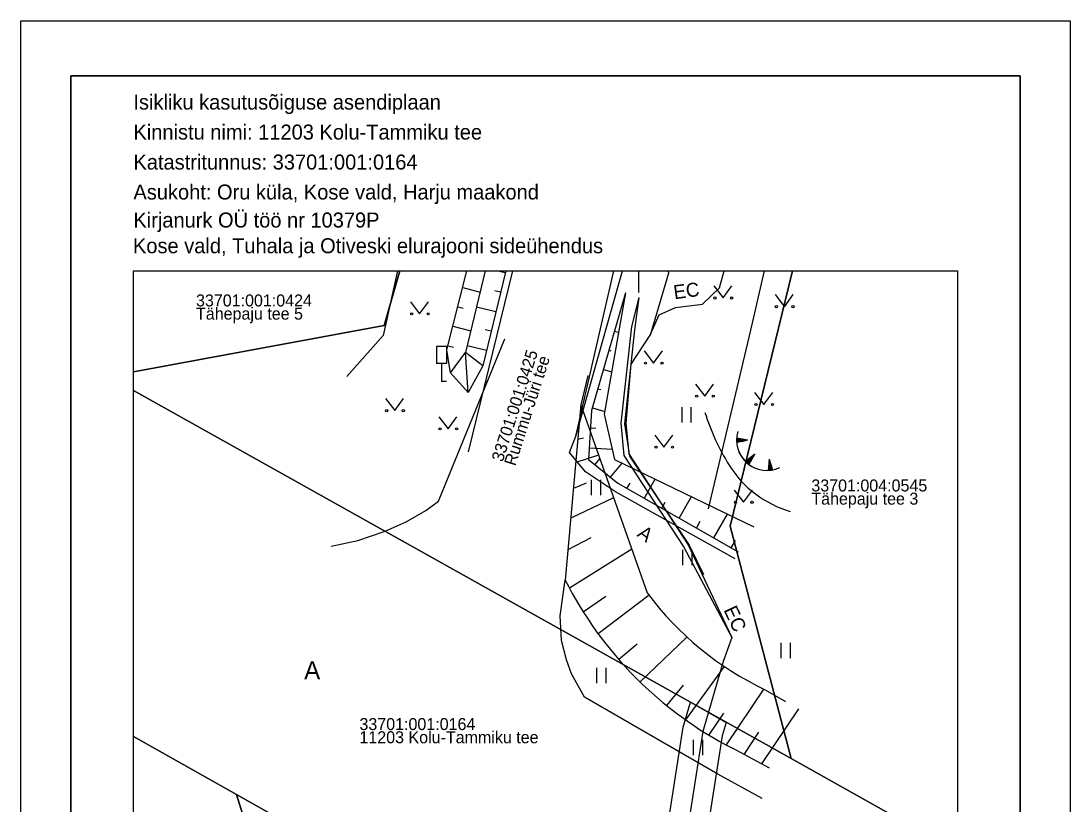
# Model space of a CAD drawing. Extents: x 556484.7 to 556537.2, y 6562224.6 to 6562298.8.
# Drawn here: x 556484.7 to 556537.2, y 6562259.6 to 6562298.8 of the extents above; entities that cross this region are included whole.
import ezdxf

# ---------------------------------------------------------------- set-up
doc = ezdxf.new("R2010")
doc.units = 0
for name, color, linetype in [('Default', 7, 'Continuous'), ('HALJASTUS', 7, 'Continuous'), ('KASUTUSALA', 7, 'Continuous'), ('LIIKLUS', 7, 'Continuous'), ('MPKAABEL', 7, 'Continuous'), ('PIIR', 7, 'Continuous'), ('POST', 7, 'Continuous'), ('PR_SIDE', 7, 'Continuous'), ('RELJEEF', 7, 'Continuous'), ('SITRASS', 7, 'Continuous'), ('TEE', 7, 'Continuous'), ('VORMISTUS', 7, 'Continuous')]:
    doc.layers.add(name, color=color, linetype=linetype)

# ---------------------------------------------------------------- blocks, each defined once
blk = doc.blocks.new('TQNGER')
at = {"layer": 'Default'}
for p, q in [((0.007, 0.229), (-0.105, 0.229)), ((0.076, 0.089), (0, 0)), ((0.219, 0.038), (0.232, -0.071))]:
    blk.add_line(p, q, dxfattribs=at)
blk.add_arc((0.197, 0.23), 0.303, 163.4234, 295.1745, dxfattribs=at)
blk = doc.blocks.new('HEIN')
at = {"layer": 'Default'}
for p, q in [((-0.046, 0.076), (-0.046, -0.076)), ((0.046, 0.076), (0.046, -0.076))]:
    blk.add_line(p, q, dxfattribs=at)

msp = doc.modelspace()

# ---------------------------------------------------------------- linework, layer by layer
at = {"layer": 'HALJASTUS'}
for p, q in [((556519.352, 6562285.578), (556519.815, 6562284.971)), ((556519.815, 6562284.971), (556520.261, 6562285.578)), ((556504.167, 6562284.783), (556504.63, 6562284.176)), ((556504.63, 6562284.176), (556505.076, 6562284.783)), ((556522.423, 6562285.141), (556522.886, 6562284.534)), ((556522.886, 6562284.534), (556523.332, 6562285.141)), ((556515.876, 6562282.317), (556516.339, 6562281.71)), ((556516.339, 6562281.71), (556516.785, 6562282.317)), ((556518.436, 6562280.662), (556518.899, 6562280.056)), ((556518.899, 6562280.056), (556519.345, 6562280.662)), ((556521.399, 6562280.247), (556521.863, 6562279.64)), ((556521.863, 6562279.64), (556522.308, 6562280.247)), ((556502.924, 6562279.94), (556503.388, 6562279.333)), ((556503.388, 6562279.333), (556503.833, 6562279.94)), ((556505.593, 6562279.03), (556506.056, 6562278.424)), ((556506.056, 6562278.424), (556506.502, 6562279.03)), ((556516.398, 6562278.112), (556516.861, 6562277.505)), ((556516.861, 6562277.505), (556517.307, 6562278.112)), ((556520.376, 6562275.353), (556520.839, 6562274.746)), ((556520.839, 6562274.746), (556521.285, 6562275.353))]:
    msp.add_line(p, q, dxfattribs=at)
for points in [[(556503.531, 6562286.331), (556502.808, 6562283.087), (556500.987, 6562281.042)], [(556519.094, 6562274.418), (556521.2, 6562283.365), (556521.895, 6562286.331)]]:
    msp.add_lwpolyline(points, dxfattribs=at)
for centre in [(556519.414, 6562284.971), (556520.243, 6562284.971), (556504.229, 6562284.176), (556505.058, 6562284.176), (556522.485, 6562284.534), (556523.314, 6562284.534), (556515.938, 6562281.71), (556516.767, 6562281.71), (556518.498, 6562280.056), (556519.327, 6562280.056), (556521.462, 6562279.64), (556522.29, 6562279.64), (556502.987, 6562279.333), (556503.815, 6562279.333), (556505.655, 6562278.424), (556506.484, 6562278.424), (556516.46, 6562277.505), (556517.289, 6562277.505), (556520.438, 6562274.746), (556521.267, 6562274.746)]:
    msp.add_circle(centre, 0.055, dxfattribs=at)
for centre, radius, start, end in [((556529.655, 6562282.566), 11.247, 197.2128, 212.0206), ((556524.683, 6562279.457), 5.383, 212.0206, 253.8232)]:
    msp.add_arc(centre, radius, start, end, dxfattribs=at)
at = {"layer": 'KASUTUSALA'}
msp.add_lwpolyline([(556514.025, 6562251.865), (556516.997, 6562258.232), (556517.824, 6562263.489), (556518.188, 6562264.736), (556519.979, 6562263.734), (556519.78, 6562263.051), (556518.929, 6562257.642), (556515.887, 6562251.125), (556515.181, 6562248.995), (556513.406, 6562249.997)], close=True, dxfattribs=at)
at = {"layer": 'LIIKLUS'}
for p, q in [((556505.483, 6562282.537), (556505.483, 6562281.687)), ((556505.983, 6562282.537), (556505.483, 6562282.537)), ((556505.983, 6562282.537), (556505.983, 6562281.687)), ((556505.983, 6562281.687), (556505.483, 6562281.687)), ((556505.733, 6562281.687), (556505.733, 6562280.787)), ((556505.983, 6562280.787), (556505.733, 6562280.787))]:
    msp.add_line(p, q, dxfattribs=at)
at = {"layer": 'MPKAABEL'}
for points in [[(556515.599, 6562284.989), (556515.233, 6562283.539), (556514.701, 6562278.702), (556514.859, 6562277.091), (556517.861, 6562272.495), (556520.264, 6562267.977), (556519.825, 6562266.774)], [(556515.599, 6562284.989), (556515.389, 6562283.377), (556514.877, 6562278.676), (556515.133, 6562277.052), (556518.125, 6562272.607), (556518.841, 6562271.133)]]:
    msp.add_lwpolyline(points, dxfattribs=at)
at = {"layer": 'PIIR'}
for points in [[(556503.64, 6562286.331), (556502.86, 6562283.59), (556490.306, 6562281.27)], [(556523.297, 6562286.331), (556520.17, 6562273.55), (556523.22, 6562261.92), (556490.306, 6562280.342)], [(556490.306, 6562281.27), (556502.86, 6562283.59), (556503.64, 6562286.331)], [(556531.556, 6562257.256), (556523.22, 6562261.92), (556520.17, 6562273.55), (556523.297, 6562286.331)], [(556490.306, 6562280.342), (556523.22, 6562261.92), (556531.556, 6562257.256)], [(556490.306, 6562263.024), (556495.46, 6562260.13), (556498.86, 6562249.27), (556495.436, 6562233.831)], [(556531.556, 6562239.92), (556521.76, 6562245.28), (556495.46, 6562260.13), (556490.306, 6562263.024)], [(556495.436, 6562233.831), (556498.86, 6562249.27), (556495.46, 6562260.13), (556521.76, 6562245.28), (556509.4, 6562242.29), (556507.535, 6562233.831)]]:
    msp.add_lwpolyline(points, dxfattribs=at)
at = {"layer": 'POST'}
for p, q in [((556515.599, 6562285.239), (556515.599, 6562286.331)), ((556515.599, 6562284.989), (556515.599, 6562284.989))]:
    msp.add_line(p, q, dxfattribs=at)
at = {"layer": 'PR_SIDE'}
msp.add_lwpolyline([(556517.063, 6562286.331), (556517.083, 6562286.219), (556516.179, 6562283.162), (556515.21, 6562281.653), (556514.952, 6562278.701), (556515.102, 6562277.176), (556518.076, 6562272.622), (556520.264, 6562267.977), (556519.825, 6562266.774), (556518.802, 6562263.27), (556517.963, 6562257.937), (556514.956, 6562251.495), (556513.945, 6562248.442), (556510.593, 6562244.734), (556508.409, 6562242.642), (556507.177, 6562241.449), (556506.515, 6562240.511), (556505.285, 6562236.107), (556504.9, 6562233.831)], dxfattribs=at)
at = {"layer": 'RELJEEF'}
for p, q in [((556508.913, 6562286.227), (556508.481, 6562286.331)), ((556506.786, 6562285.489), (556507.661, 6562285.267)), ((556508.679, 6562285.255), (556508.39, 6562285.324)), ((556506.54, 6562284.52), (556506.805, 6562284.453)), ((556508.445, 6562284.282), (556507.478, 6562284.515)), ((556514.656, 6562284.273), (556514.687, 6562284.264)), ((556506.294, 6562283.551), (556507.188, 6562283.324)), ((556508.211, 6562283.31), (556507.92, 6562283.38)), ((556514.38, 6562283.312), (556514.588, 6562283.252)), ((556506.048, 6562282.582), (556506.319, 6562282.513)), ((556506.179, 6562281.221), (556506.925, 6562282.244)), ((556507.794, 6562281.573), (556506.925, 6562282.244)), ((556507.062, 6562280.245), (556506.925, 6562282.244)), ((556507.978, 6562282.338), (556507.005, 6562282.572)), ((556514.104, 6562282.35), (556514.198, 6562282.324)), ((556513.828, 6562281.389), (556514.243, 6562281.27)), ((556507.945, 6562280.817), (556508.016, 6562280.763)), ((556513.552, 6562280.428), (556513.708, 6562280.383)), ((556513.276, 6562279.467), (556513.899, 6562279.288)), ((556513.186, 6562278.474), (556513.442, 6562278.458)), ((556512.828, 6562277.961), (556512.543, 6562277.887)), ((556512.828, 6562277.961), (556512.543, 6562277.887)), ((556520.496, 6562277.861), (556520.596, 6562277.94)), ((556520.497, 6562277.893), (556520.564, 6562277.947)), ((556520.497, 6562277.829), (556520.628, 6562277.934)), ((556520.497, 6562277.798), (556520.66, 6562277.928)), ((556520.498, 6562277.926), (556520.531, 6562277.953)), ((556521.057, 6562277.851), (556520.5, 6562277.959)), ((556513.125, 6562277.476), (556514.272, 6562277.406)), ((556520.499, 6562277.767), (556520.692, 6562277.922)), ((556521.057, 6562277.851), (556520.5, 6562277.742)), ((556520.511, 6562277.744), (556520.725, 6562277.915)), ((556520.564, 6562277.755), (556520.757, 6562277.909)), ((556520.617, 6562277.765), (556520.789, 6562277.903)), ((556520.67, 6562277.775), (556520.821, 6562277.897)), ((556520.723, 6562277.786), (556520.854, 6562277.891)), ((556520.776, 6562277.796), (556520.886, 6562277.884)), ((556520.829, 6562277.807), (556520.918, 6562277.878)), ((556520.882, 6562277.817), (556520.95, 6562277.872)), ((556520.935, 6562277.827), (556520.983, 6562277.866)), ((556520.988, 6562277.838), (556521.015, 6562277.859)), ((556513.585, 6562277.111), (556512.441, 6562276.745)), ((556513.585, 6562277.111), (556512.441, 6562276.745)), ((556513.411, 6562276.629), (556513.654, 6562276.927)), ((556521.389, 6562277.131), (556520.944, 6562276.779)), ((556521.065, 6562276.672), (556521.072, 6562276.881)), ((556521.089, 6562276.653), (556521.098, 6562276.901)), ((556521.389, 6562277.131), (556521.109, 6562276.638)), ((556521.114, 6562276.647), (556521.124, 6562276.921)), ((556521.141, 6562276.694), (556521.149, 6562276.942)), ((556521.167, 6562276.741), (556521.175, 6562276.962)), ((556521.194, 6562276.788), (556521.201, 6562276.982)), ((556521.221, 6562276.835), (556521.226, 6562277.003)), ((556521.247, 6562276.882), (556521.252, 6562277.023)), ((556521.274, 6562276.929), (556521.278, 6562277.044)), ((556521.301, 6562276.976), (556521.304, 6562277.064)), ((556521.327, 6562277.023), (556521.329, 6562277.084)), ((556521.354, 6562277.07), (556521.355, 6562277.105)), ((556522.121, 6562276.907), (556522.078, 6562276.342)), ((556522.121, 6562276.907), (556522.294, 6562276.367)), ((556514.185, 6562275.996), (556514.763, 6562276.703)), ((556520.968, 6562276.756), (556520.969, 6562276.799)), ((556520.992, 6562276.734), (556520.995, 6562276.819)), ((556521.016, 6562276.713), (556521.021, 6562276.84)), ((556521.04, 6562276.692), (556521.046, 6562276.86)), ((556522.111, 6562276.344), (556522.081, 6562276.374)), ((556522.144, 6562276.346), (556522.083, 6562276.406)), ((556522.176, 6562276.35), (556522.086, 6562276.439)), ((556522.208, 6562276.354), (556522.088, 6562276.472)), ((556522.239, 6562276.358), (556522.091, 6562276.505)), ((556522.269, 6562276.363), (556522.093, 6562276.537)), ((556522.29, 6562276.377), (556522.095, 6562276.57)), ((556522.274, 6562276.429), (556522.098, 6562276.603)), ((556522.257, 6562276.48), (556522.1, 6562276.636)), ((556522.241, 6562276.532), (556522.103, 6562276.668)), ((556522.224, 6562276.583), (556522.105, 6562276.701)), ((556522.208, 6562276.635), (556522.108, 6562276.734)), ((556522.192, 6562276.686), (556522.11, 6562276.767)), ((556522.175, 6562276.738), (556522.113, 6562276.799)), ((556522.159, 6562276.789), (556522.115, 6562276.832)), ((556522.142, 6562276.84), (556522.118, 6562276.865)), ((556515.877, 6562274.94), (556516.425, 6562275.901)), ((556512.96, 6562275.707), (556512.325, 6562275.435)), ((556512.96, 6562275.707), (556512.325, 6562275.435)), ((556515.009, 6562275.436), (556515.163, 6562275.706)), ((556514.342, 6562274.972), (556512.192, 6562273.947)), ((556514.342, 6562274.972), (556512.192, 6562273.947)), ((556517.615, 6562273.95), (556518.23, 6562275.029)), ((556516.746, 6562274.445), (556516.921, 6562274.751)), ((556518.484, 6562273.454), (556518.678, 6562273.796)), ((556519.352, 6562272.959), (556520.035, 6562274.157)), ((556513.194, 6562272.969), (556512.051, 6562272.361)), ((556513.194, 6562272.969), (556512.051, 6562272.361)), ((556520.221, 6562272.464), (556520.436, 6562272.841)), ((556515.255, 6562272.393), (556512.131, 6562270.441)), ((556515.255, 6562272.393), (556512.131, 6562270.441)), ((556516.117, 6562270.094), (556513.566, 6562268.167)), ((556516.117, 6562270.094), (556513.566, 6562268.167)), ((556513.944, 6562270.029), (556512.824, 6562269.255)), ((556513.944, 6562270.029), (556512.824, 6562269.255)), ((556518.011, 6562267.998), (556515.665, 6562265.756)), ((556518.011, 6562267.998), (556515.665, 6562265.756)), ((556515.522, 6562267.647), (556514.599, 6562266.879)), ((556515.522, 6562267.647), (556514.599, 6562266.879)), ((556519.866, 6562266.535), (556517.944, 6562263.859)), ((556519.866, 6562266.535), (556517.944, 6562263.859)), ((556517.824, 6562265.595), (556516.993, 6562264.579)), ((556517.824, 6562265.595), (556516.993, 6562264.579)), ((556521.851, 6562265.404), (556519.969, 6562262.604)), ((556521.851, 6562265.404), (556519.969, 6562262.604)), ((556523.592, 6562264.411), (556521.74, 6562261.654)), ((556523.592, 6562264.411), (556521.74, 6562261.654)), ((556519.833, 6562264.194), (556519.098, 6562263.101)), ((556519.833, 6562264.194), (556519.098, 6562263.101)), ((556521.599, 6562263.237), (556520.856, 6562262.131)), ((556521.599, 6562263.237), (556520.856, 6562262.131))]:
    msp.add_line(p, q, dxfattribs=at)
for points in [[(556508.938, 6562286.331), (556507.794, 6562281.573), (556507.062, 6562280.245), (556506.179, 6562281.221), (556505.997, 6562282.381), (556507, 6562286.331)], [(556507.919, 6562286.331), (556506.925, 6562282.244)], [(556514.932, 6562285.234), (556513.238, 6562279.336), (556513.089, 6562276.892), (556514.552, 6562275.696), (556520.579, 6562272.26)], [(556514.932, 6562285.234), (556513.875, 6562279.148), (556514.391, 6562276.883), (556521.359, 6562273.518)], [(556512.697, 6562279.621), (556516.026, 6562270.216)], [(556512.697, 6562279.621), (556516.026, 6562270.216)], [(556521.93, 6562265.367), (556522.949, 6562264.781)], [(556521.93, 6562265.367), (556522.949, 6562264.781)], [(556522.144, 6562261.435), (556520.286, 6562262.438)], [(556522.144, 6562261.435), (556520.286, 6562262.438)]]:
    msp.add_lwpolyline(points, dxfattribs=at)
for centre, radius, start, end in [((556522.01, 6562277.854), 1.514, 163.4234, 295.1745), ((556529.057, 6562279.532), 19.213, 206.8613, 242.8382), ((556529.057, 6562279.532), 19.213, 206.8613, 242.8382), ((556528.493, 6562279.376), 15.47, 216.3078, 244.8992), ((556528.493, 6562279.376), 15.47, 216.3078, 244.8992)]:
    msp.add_arc(centre, radius, start, end, dxfattribs=at)
at = {"layer": 'SITRASS'}
for points in [[(556516.179, 6562283.162), (556516.617, 6562284.125), (556517.438, 6562284.488), (556518.785, 6562284.668), (556519.645, 6562285.484), (556519.874, 6562286.331)], [(556516.179, 6562283.162), (556515.21, 6562281.653), (556514.952, 6562278.701), (556515.102, 6562277.176), (556518.076, 6562272.622), (556520.264, 6562267.977), (556519.825, 6562266.774), (556518.802, 6562263.27), (556517.963, 6562257.937), (556514.956, 6562251.495), (556513.945, 6562248.442), (556510.593, 6562244.734), (556508.409, 6562242.642), (556507.177, 6562241.449), (556506.515, 6562240.511), (556505.285, 6562236.107), (556504.9, 6562233.831)]]:
    msp.add_lwpolyline(points, dxfattribs=at)
at = {"layer": 'TEE'}
for points in [[(556509.285, 6562286.331), (556507.061, 6562277.268)], [(556520.429, 6562271.918), (556514.428, 6562275.276), (556512.941, 6562276.277), (556512.13, 6562277.241), (556512.448, 6562278.055), (556514.353, 6562286.331)], [(556512.448, 6562278.055), (556514.793, 6562286.331)], [(556505.575, 6562274.799), (556508.899, 6562282.92)], [(556505.575, 6562274.799), (556508.899, 6562282.92)], [(556513.045, 6562281.083), (556512.697, 6562279.621), (556511.917, 6562270.851)], [(556513.045, 6562281.083), (556512.697, 6562279.621), (556511.917, 6562270.851)], [(556500.202, 6562272.554), (556501.533, 6562272.827), (556502.9, 6562273.293), (556503.952, 6562273.77), (556504.947, 6562274.343), (556505.575, 6562274.799), (556505.575, 6562274.799)], [(556500.202, 6562272.554), (556501.533, 6562272.827), (556502.9, 6562273.293), (556503.952, 6562273.77), (556504.947, 6562274.343), (556505.575, 6562274.799), (556505.575, 6562274.799)], [(556512.885, 6562265.002), (556512.236, 6562266.163), (556511.974, 6562266.87), (556511.737, 6562267.835), (556511.659, 6562269.072), (556511.917, 6562270.852)], [(556512.885, 6562265.002), (556512.236, 6562266.163), (556511.974, 6562266.87), (556511.737, 6562267.835), (556511.659, 6562269.072), (556511.917, 6562270.852)], [(556521.78, 6562259.922), (556519.559, 6562261.142), (556512.885, 6562265.002)], [(556521.78, 6562259.922), (556519.559, 6562261.142), (556512.885, 6562265.002)]]:
    msp.add_lwpolyline(points, dxfattribs=at)
at = {"layer": 'VORMISTUS'}
for points in [[(556484.681, 6562298.831), (556537.181, 6562298.831), (556537.181, 6562224.581), (556484.681, 6562224.581)], [(556487.181, 6562227.331), (556534.681, 6562227.331), (556534.681, 6562296.081), (556487.181, 6562296.081)], [(556487.181, 6562296.081), (556534.681, 6562296.081), (556534.681, 6562227.331), (556487.181, 6562227.331)], [(556531.556, 6562233.831), (556490.306, 6562233.831), (556490.306, 6562286.331), (556531.556, 6562286.331)]]:
    msp.add_lwpolyline(points, close=True, dxfattribs=at)

# ---------------------------------------------------------------- block references
at = {"layer": 'HALJASTUS', "xscale": 5, "yscale": 5}
for p in [(556517.978, 6562279.124), (556513.452, 6562275.487), (556518.023, 6562271.983), (556522.939, 6562267.327), (556513.716, 6562266.078), (556518.554, 6562262.471)]:
    msp.add_blockref('HEIN', p, dxfattribs=at)
at = {"layer": 'RELJEEF', "xscale": 5, "yscale": 5}
msp.add_blockref('TQNGER', (556521.023, 6562276.706), dxfattribs=at)

# ---------------------------------------------------------------- texts
at = {"layer": 'PIIR'}
for s, p in [('33701:001:0424', (556493.441, 6562284.547)), ('Tähepaju tee 5', (556493.441, 6562283.887)), ('33701:004:0545', (556524.236, 6562275.288)), ('Tähepaju tee 3', (556524.236, 6562274.628)), ('33701:001:0164', (556501.62, 6562263.348)), ('11203 Kolu-Tammiku tee', (556501.62, 6562262.688))]:
    msp.add_text(s, height=0.6, dxfattribs=at).set_placement(p)
for s, p in [('33701:001:0425', (556508.789, 6562276.731)), ('Rummu-Jüri tee', (556509.417, 6562276.53))]:
    msp.add_text(s, height=0.6, rotation=72.1892, dxfattribs=at).set_placement(p)
at = {"layer": 'SITRASS'}
for rotation, p in [(7.5657, (556517.383, 6562284.904)), (295.1709, (556519.831, 6562269.362))]:
    msp.add_text('EC', height=0.7, rotation=rotation, dxfattribs=at).set_placement(p)
at = {"layer": 'TEE'}
msp.add_text('A', height=0.7, rotation=323.8729, dxfattribs=at).set_placement((556515.475, 6562273.076))
msp.add_text('A', height=0.9, dxfattribs=at).set_placement((556498.854, 6562265.89))
at = {"layer": 'VORMISTUS'}
for s, p in [('Isikliku kasutusõiguse asendiplaan', (556490.309, 6562294.398)), ('Kirjanurk OÜ töö nr 10379P', (556490.305, 6562288.496)), ('Kose vald, Tuhala ja Otiveski elurajooni sideühendus', (556490.286, 6562287.209))]:
    msp.add_text(s, height=0.75, rotation=360, dxfattribs=at).set_placement(p)
for s, p in [('Kinnistu nimi: 11203 Kolu-Tammiku tee', (556490.309, 6562292.898)), ('Katastritunnus: 33701:001:0164', (556490.309, 6562291.398)), ('Asukoht: Oru küla, Kose vald, Harju maakond', (556490.309, 6562289.898))]:
    msp.add_text(s, height=0.75, dxfattribs=at).set_placement(p)

doc.saveas('drawing.dxf')
